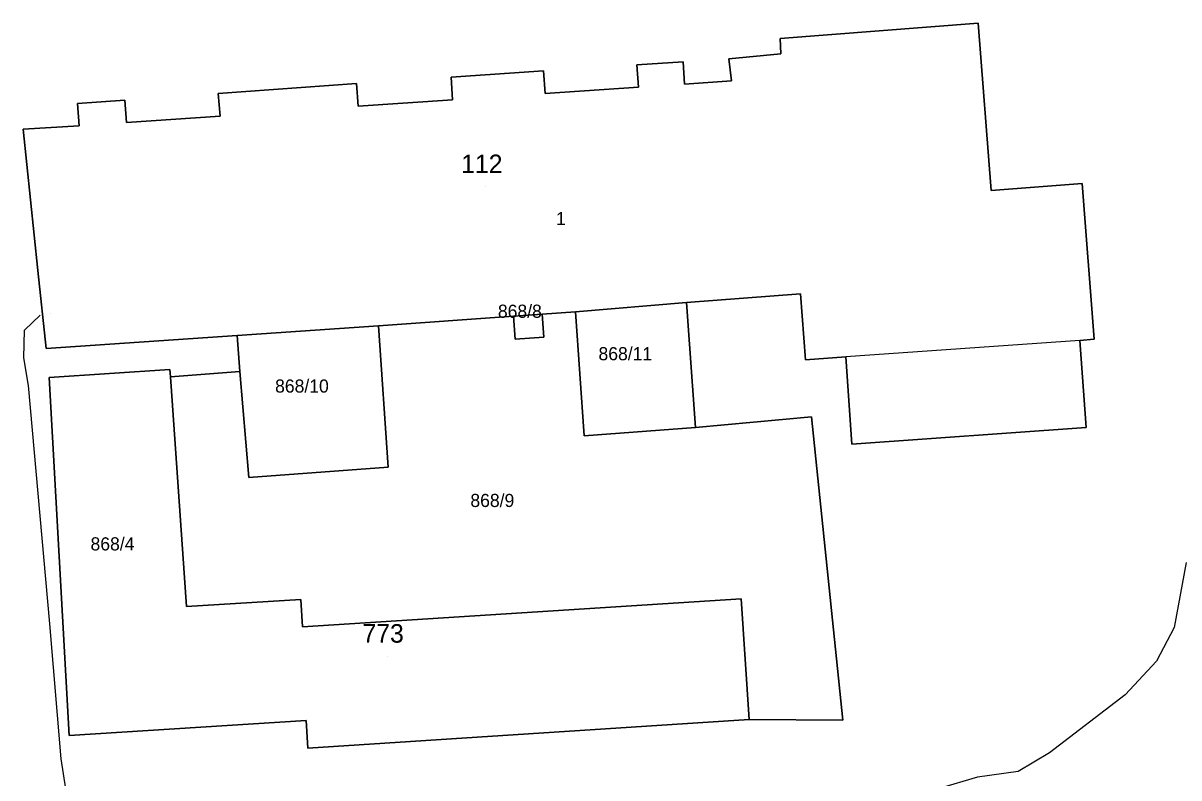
# Model space of a CAD drawing. Extents: x -873642 to -872917, y -1012962 to -1012567.
# Drawn here: x -873556.2 to -873481.3, y -1012716.8 to -1012667.9 of the extents above; entities that cross this region are included whole.
import ezdxf

# ---------------------------------------------------------------- set-up
doc = ezdxf.new("R2010")
doc.units = 0
for name, color, linetype in [('adresni_misto', 7, 'Continuous'), ('cisla_parcelni_kn', 7, 'Continuous'), ('cislo_domovni', 7, 'Continuous'), ('parcely_kn', 7, 'Continuous'), ('ROZVADEC', 7, 'Continuous'), ('stavebni_objekty_bydleni', 7, 'Continuous'), ('stavebni_objekty_ostatni', 7, 'Continuous'), ('stavebni_objekty_sluzby', 7, 'Continuous'), ('stavebni_objekty_vyroba', 7, 'Continuous'), ('TRASY - zamereno', 7, 'Continuous')]:
    doc.layers.add(name, color=color, linetype=linetype)

msp = doc.modelspace()

# ---------------------------------------------------------------- linework, layer by layer
at = {"layer": 'adresni_misto'}
for p, q in [((-873526.2, -1012678.52), (-873526.2, -1012678.52)), ((-873532.59, -1012708.92), (-873532.59, -1012708.92))]:
    msp.add_line(p, q, dxfattribs=at)
at = {"layer": 'parcely_kn'}
for points in [[(-873554.67, -1012688.98), (-873542.3, -1012688.13), (-873542.12, -1012690.46), (-873546.61, -1012690.82), (-873546.65, -1012690.34), (-873554.47, -1012690.85), (-873553.17, -1012714.04), (-873537.84, -1012713.05), (-873537.72, -1012714.85), (-873509.15, -1012713), (-873503.09, -1012713.04), (-873505.11, -1012693.39), (-873512.62, -1012694.08), (-873513.22, -1012685.99), (-873505.83, -1012685.44), (-873505.51, -1012689.7), (-873502.9, -1012689.52), (-873502.5, -1012695.17), (-873487.34, -1012694.1), (-873487.74, -1012688.45), (-873486.82, -1012688.38), (-873487.59, -1012678.29), (-873493.48, -1012678.74), (-873494.32, -1012667.91), (-873507.15, -1012668.91), (-873507.11, -1012669.89), (-873510.47, -1012670.23), (-873510.29, -1012671.64), (-873513.34, -1012671.86), (-873513.43, -1012670.42), (-873516.42, -1012670.61), (-873516.32, -1012672.05), (-873522.37, -1012672.47), (-873522.47, -1012671.01), (-873528.44, -1012671.41), (-873528.37, -1012672.87), (-873534.47, -1012673.29), (-873534.58, -1012671.81), (-873543.54, -1012672.46), (-873543.41, -1012673.93), (-873549.47, -1012674.35), (-873549.58, -1012672.9), (-873552.63, -1012673.11), (-873552.53, -1012674.56), (-873556.16, -1012674.78), (-873555.2, -1012683.93)], [(-873487.74, -1012688.45), (-873487.34, -1012694.1), (-873502.5, -1012695.17), (-873502.9, -1012689.52), (-873505.51, -1012689.7), (-873505.83, -1012685.44), (-873513.22, -1012685.99), (-873520.39, -1012686.61), (-873522.55, -1012686.76), (-873524.41, -1012686.89), (-873533.16, -1012687.5), (-873542.3, -1012688.13), (-873554.67, -1012688.98), (-873555.2, -1012683.93), (-873556.16, -1012674.78), (-873552.53, -1012674.56), (-873552.63, -1012673.11), (-873549.58, -1012672.9), (-873549.47, -1012674.35), (-873543.41, -1012673.93), (-873543.54, -1012672.46), (-873534.58, -1012671.81), (-873534.47, -1012673.29), (-873528.37, -1012672.87), (-873528.44, -1012671.41), (-873522.47, -1012671.01), (-873522.37, -1012672.47), (-873516.32, -1012672.05), (-873516.42, -1012670.61), (-873513.43, -1012670.42), (-873513.34, -1012671.86), (-873510.29, -1012671.64), (-873510.47, -1012670.23), (-873507.11, -1012669.89), (-873507.15, -1012668.91), (-873494.32, -1012667.91), (-873493.48, -1012678.74), (-873487.59, -1012678.29), (-873486.82, -1012688.38)], [(-873554.67, -1012688.98), (-873542.3, -1012688.13), (-873542.12, -1012690.46), (-873546.61, -1012690.82), (-873546.65, -1012690.34), (-873554.47, -1012690.85), (-873553.17, -1012714.04), (-873537.84, -1012713.05), (-873537.72, -1012714.85), (-873509.15, -1012713), (-873503.09, -1012713.04), (-873505.11, -1012693.39), (-873512.62, -1012694.08), (-873513.22, -1012685.99), (-873505.83, -1012685.44), (-873505.51, -1012689.7), (-873502.9, -1012689.52), (-873502.5, -1012695.17), (-873487.34, -1012694.1), (-873487.74, -1012688.45), (-873486.82, -1012688.38), (-873487.59, -1012678.29), (-873493.48, -1012678.74), (-873494.32, -1012667.91), (-873507.15, -1012668.91), (-873507.11, -1012669.89), (-873510.47, -1012670.23), (-873510.29, -1012671.64), (-873513.34, -1012671.86), (-873513.43, -1012670.42), (-873516.42, -1012670.61), (-873516.32, -1012672.05), (-873522.37, -1012672.47), (-873522.47, -1012671.01), (-873528.44, -1012671.41), (-873528.37, -1012672.87), (-873534.47, -1012673.29), (-873534.58, -1012671.81), (-873543.54, -1012672.46), (-873543.41, -1012673.93), (-873549.47, -1012674.35), (-873549.58, -1012672.9), (-873552.63, -1012673.11), (-873552.53, -1012674.56), (-873556.16, -1012674.78), (-873555.2, -1012683.93)], [(-873487.74, -1012688.45), (-873487.34, -1012694.1), (-873502.5, -1012695.17), (-873502.9, -1012689.52), (-873505.51, -1012689.7), (-873505.83, -1012685.44), (-873513.22, -1012685.99), (-873520.39, -1012686.61), (-873522.55, -1012686.76), (-873524.41, -1012686.89), (-873533.16, -1012687.5), (-873542.3, -1012688.13), (-873554.67, -1012688.98), (-873555.2, -1012683.93), (-873556.16, -1012674.78), (-873552.53, -1012674.56), (-873552.63, -1012673.11), (-873549.58, -1012672.9), (-873549.47, -1012674.35), (-873543.41, -1012673.93), (-873543.54, -1012672.46), (-873534.58, -1012671.81), (-873534.47, -1012673.29), (-873528.37, -1012672.87), (-873528.44, -1012671.41), (-873522.47, -1012671.01), (-873522.37, -1012672.47), (-873516.32, -1012672.05), (-873516.42, -1012670.61), (-873513.43, -1012670.42), (-873513.34, -1012671.86), (-873510.29, -1012671.64), (-873510.47, -1012670.23), (-873507.11, -1012669.89), (-873507.15, -1012668.91), (-873494.32, -1012667.91), (-873493.48, -1012678.74), (-873487.59, -1012678.29), (-873486.82, -1012688.38)], [(-873513.22, -1012685.99), (-873512.62, -1012694.08), (-873519.83, -1012694.62), (-873520.39, -1012686.61)], [(-873513.22, -1012685.99), (-873512.62, -1012694.08), (-873519.83, -1012694.62), (-873520.39, -1012686.61)], [(-873512.62, -1012694.08), (-873505.11, -1012693.39), (-873503.09, -1012713.04), (-873509.15, -1012713), (-873509.68, -1012705.19), (-873538.07, -1012707), (-873538.18, -1012705.22), (-873545.59, -1012705.69), (-873546.61, -1012690.82), (-873542.12, -1012690.46), (-873541.55, -1012697.33), (-873532.52, -1012696.65), (-873533.16, -1012687.5), (-873524.41, -1012686.89), (-873524.3, -1012688.37), (-873522.44, -1012688.24), (-873522.55, -1012686.76), (-873520.39, -1012686.61), (-873519.83, -1012694.62)], [(-873512.62, -1012694.08), (-873505.11, -1012693.39), (-873503.09, -1012713.04), (-873509.15, -1012713), (-873509.68, -1012705.19), (-873538.07, -1012707), (-873538.18, -1012705.22), (-873545.59, -1012705.69), (-873546.61, -1012690.82), (-873542.12, -1012690.46), (-873541.55, -1012697.33), (-873532.52, -1012696.65), (-873533.16, -1012687.5), (-873524.41, -1012686.89), (-873524.3, -1012688.37), (-873522.44, -1012688.24), (-873522.55, -1012686.76), (-873520.39, -1012686.61), (-873519.83, -1012694.62)], [(-873522.55, -1012686.76), (-873522.44, -1012688.24), (-873524.3, -1012688.37), (-873524.41, -1012686.89)], [(-873522.55, -1012686.76), (-873522.44, -1012688.24), (-873524.3, -1012688.37), (-873524.41, -1012686.89)], [(-873532.52, -1012696.65), (-873541.55, -1012697.33), (-873542.12, -1012690.46), (-873542.3, -1012688.13), (-873533.16, -1012687.5)], [(-873532.52, -1012696.65), (-873541.55, -1012697.33), (-873542.12, -1012690.46), (-873542.3, -1012688.13), (-873533.16, -1012687.5)], [(-873546.65, -1012690.34), (-873546.61, -1012690.82), (-873545.59, -1012705.69), (-873538.18, -1012705.22), (-873538.07, -1012707), (-873509.68, -1012705.19), (-873509.15, -1012713), (-873537.72, -1012714.85), (-873537.84, -1012713.05), (-873553.17, -1012714.04), (-873554.47, -1012690.85)], [(-873546.65, -1012690.34), (-873546.61, -1012690.82), (-873545.59, -1012705.69), (-873538.18, -1012705.22), (-873538.07, -1012707), (-873509.68, -1012705.19), (-873509.15, -1012713), (-873537.72, -1012714.85), (-873537.84, -1012713.05), (-873553.17, -1012714.04), (-873554.47, -1012690.85)]]:
    msp.add_lwpolyline(points, close=True, dxfattribs=at)
at = {"layer": 'ROZVADEC'}
msp.add_line((-873554.4, -1012686.73), (-873554.4, -1012686.73), dxfattribs=at)
at = {"layer": 'stavebni_objekty_bydleni'}
msp.add_lwpolyline([(-873509.15, -1012713), (-873537.72, -1012714.85), (-873537.84, -1012713.05), (-873553.17, -1012714.04), (-873554.47, -1012690.85), (-873546.65, -1012690.34), (-873546.61, -1012690.82), (-873545.59, -1012705.69), (-873538.18, -1012705.22), (-873538.07, -1012707), (-873509.68, -1012705.19)], close=True, dxfattribs=at)
at = {"layer": 'stavebni_objekty_ostatni'}
msp.add_lwpolyline([(-873542.12, -1012690.46), (-873542.3, -1012688.13), (-873533.16, -1012687.5), (-873532.52, -1012696.65), (-873541.55, -1012697.33)], close=True, dxfattribs=at)
at = {"layer": 'stavebni_objekty_sluzby'}
msp.add_lwpolyline([(-873505.51, -1012689.7), (-873505.83, -1012685.44), (-873513.22, -1012685.99), (-873520.39, -1012686.61), (-873522.55, -1012686.76), (-873524.41, -1012686.89), (-873533.16, -1012687.5), (-873542.3, -1012688.13), (-873554.67, -1012688.98), (-873555.2, -1012683.93), (-873556.16, -1012674.78), (-873552.53, -1012674.56), (-873552.63, -1012673.11), (-873549.58, -1012672.9), (-873549.47, -1012674.35), (-873543.41, -1012673.93), (-873543.54, -1012672.46), (-873534.58, -1012671.81), (-873534.47, -1012673.29), (-873528.37, -1012672.87), (-873528.44, -1012671.41), (-873522.47, -1012671.01), (-873522.37, -1012672.47), (-873516.32, -1012672.05), (-873516.42, -1012670.61), (-873513.43, -1012670.42), (-873513.34, -1012671.86), (-873510.29, -1012671.64), (-873510.47, -1012670.23), (-873507.11, -1012669.89), (-873507.15, -1012668.91), (-873494.32, -1012667.91), (-873493.48, -1012678.74), (-873487.59, -1012678.29), (-873486.82, -1012688.38), (-873487.74, -1012688.45), (-873502.9, -1012689.52)], close=True, dxfattribs=at)
at = {"layer": 'stavebni_objekty_vyroba'}
msp.add_lwpolyline([(-873520.39, -1012686.61), (-873513.22, -1012685.99), (-873512.62, -1012694.08), (-873519.83, -1012694.62)], close=True, dxfattribs=at)
at = {"layer": 'TRASY - zamereno'}
for p, q in [((-873556.07, -1012687.79), (-873555.05, -1012686.82)), ((-873556.11, -1012689.57), (-873556.07, -1012687.79)), ((-873555.81, -1012691.38), (-873556.11, -1012689.57)), ((-873554.42, -1012706.8), (-873555.81, -1012691.38)), ((-873480.86, -1012702.84), (-873481.63, -1012707.04)), ((-873553.69, -1012715.54), (-873554.42, -1012706.8)), ((-873481.63, -1012707.04), (-873482.78, -1012709.21)), ((-873482.78, -1012709.21), (-873484.8, -1012711.4)), ((-873484.8, -1012711.4), (-873489.71, -1012715.15)), ((-873552.87, -1012720.83), (-873553.69, -1012715.54)), ((-873489.71, -1012715.15), (-873491.74, -1012716.37)), ((-873494.36, -1012716.73), (-873496.85, -1012717.46)), ((-873491.74, -1012716.37), (-873494.36, -1012716.73))]:
    msp.add_line(p, q, dxfattribs=at)

# ---------------------------------------------------------------- texts
at = {"layer": 'cisla_parcelni_kn'}
for s, p in [('1', (-873521.658, -1012680.988)), ('1', (-873521.658, -1012680.988)), ('868/8', (-873525.421, -1012686.988)), ('868/8', (-873525.421, -1012686.988)), ('868/11', (-873518.908, -1012689.738)), ('868/11', (-873518.908, -1012689.738)), ('868/10', (-873539.846, -1012691.831)), ('868/10', (-873539.846, -1012691.831)), ('868/9', (-873527.202, -1012699.238)), ('868/9', (-873527.202, -1012699.238)), ('868/4', (-873551.796, -1012702.05)), ('868/4', (-873551.796, -1012702.05))]:
    msp.add_text(s, height=0.85, dxfattribs=at).set_placement(p)
at = {"layer": 'cislo_domovni'}
for s, p in [('112', (-873527.8, -1012677.62)), ('773', (-873534.19, -1012708.02))]:
    msp.add_text(s, height=1.2, dxfattribs=at).set_placement(p)

doc.saveas('drawing.dxf')
